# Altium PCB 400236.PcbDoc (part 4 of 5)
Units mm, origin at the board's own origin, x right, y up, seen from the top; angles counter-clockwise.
Board outline 136.53 x 63.5 mm, 4 copper layers (Top Layer, Mid-Layer 1, Mid-Layer 2, Bottom Layer), stack 1.505 mm thick; 340 components, 230 nets, 1369 pads, 1292 vias.
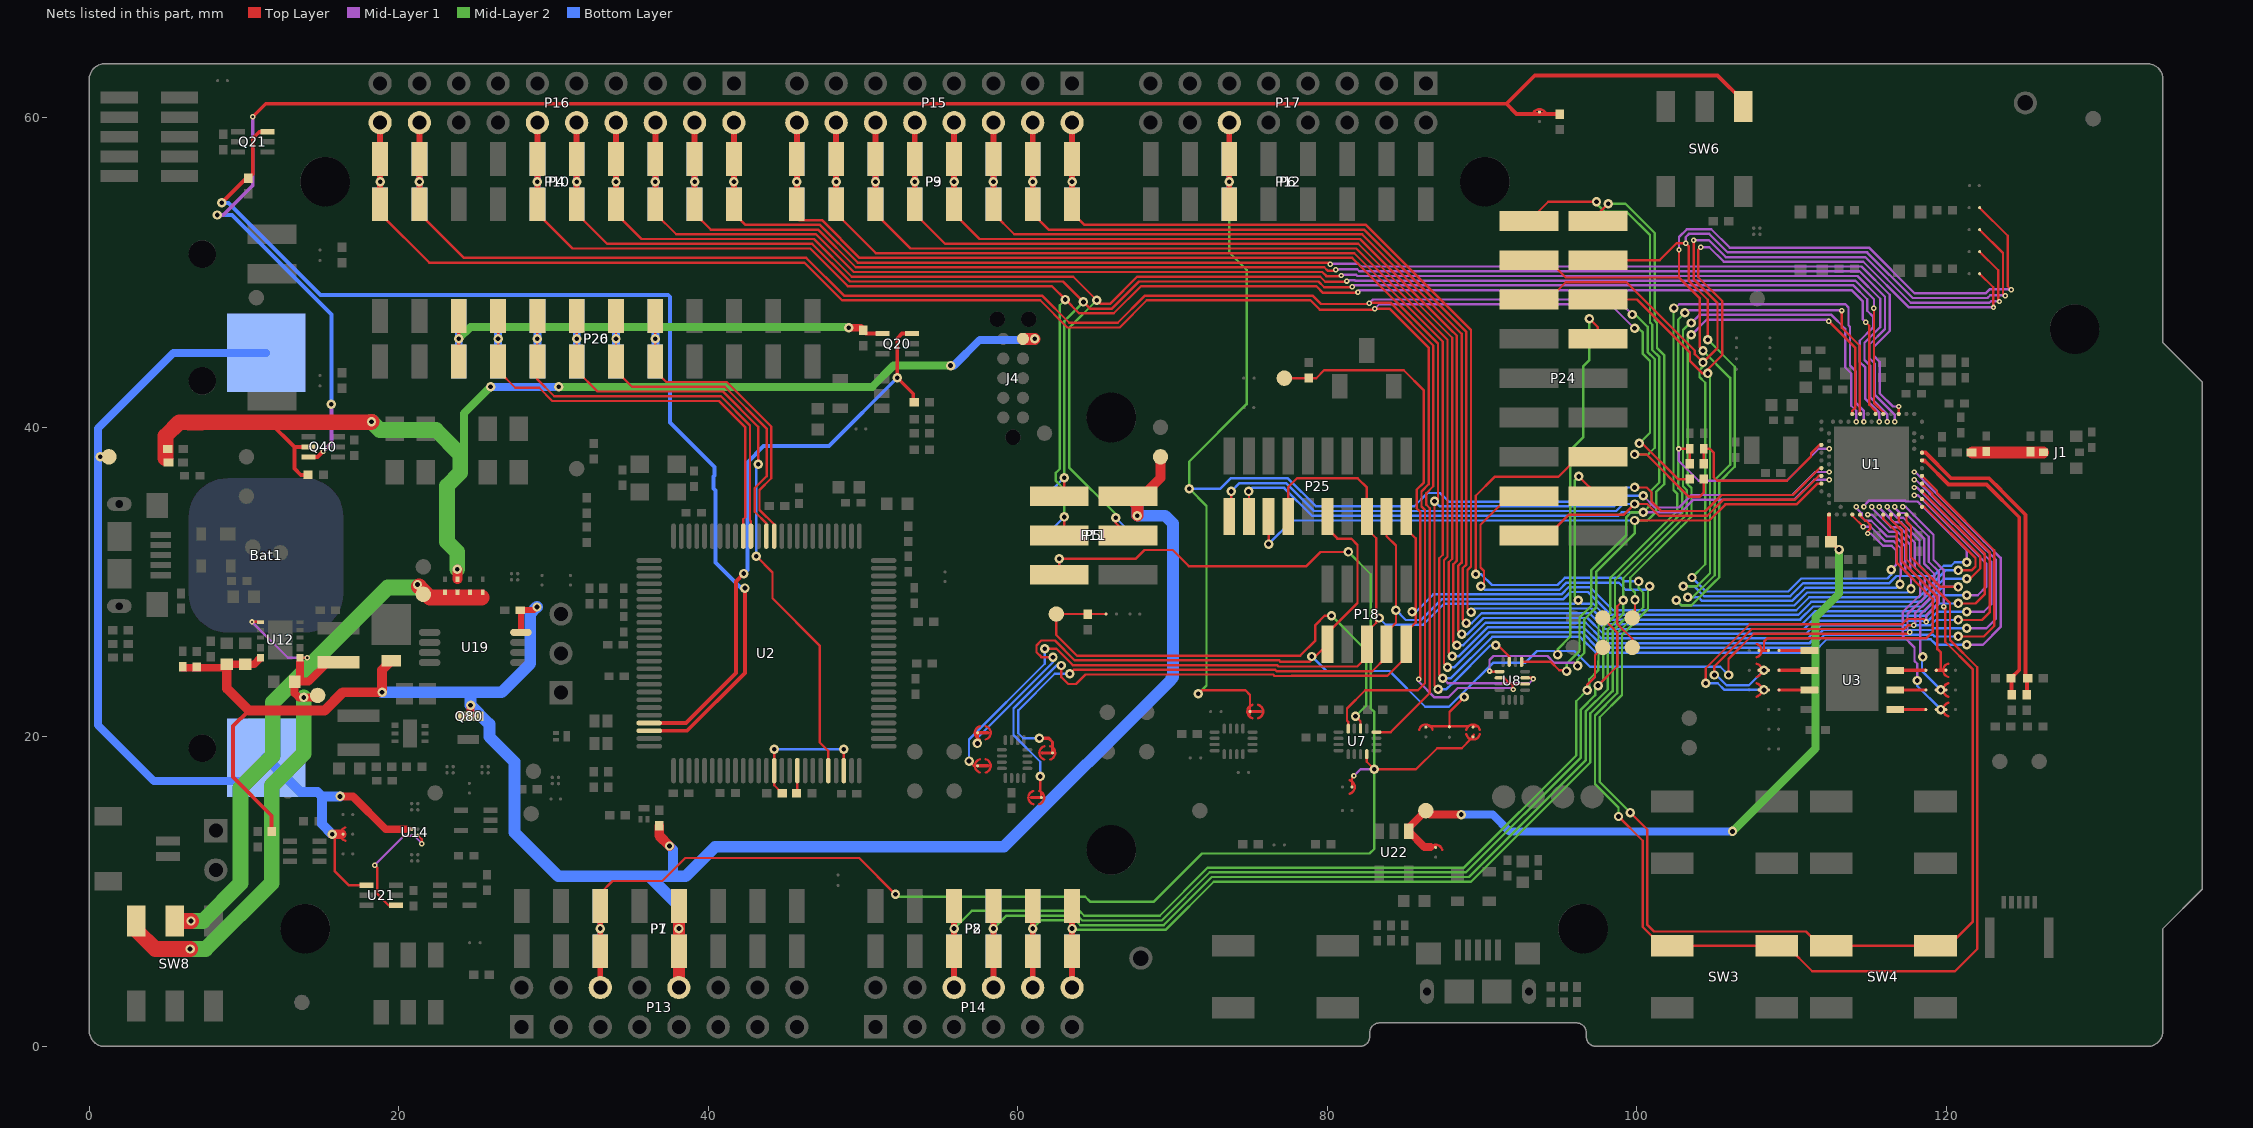
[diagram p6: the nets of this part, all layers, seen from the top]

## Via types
v1: diameter 0.61, hole 0.305, Top Layer to Bottom Layer, tented both sides, 1088 vias
v2: diameter 0.35, hole 0.15, Top Layer to Mid-Layer 1, tented both sides, 180 vias
v3: diameter 0.61, hole 0.305, Top Layer to Bottom Layer, 24 vias

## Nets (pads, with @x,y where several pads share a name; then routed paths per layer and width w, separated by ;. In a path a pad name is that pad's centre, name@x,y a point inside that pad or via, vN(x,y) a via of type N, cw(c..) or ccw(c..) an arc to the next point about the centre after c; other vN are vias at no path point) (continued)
P0.08: P6.6 P12.6 P17.12 SB52.1 U1.N1 | length 93.5
  Top Layer w0.15: 110.082,35.636 111.814,37.367 U1.N1@111.914,37.367
  Top Layer w0.152: v1(71.653,22.784) 71.884,23.014 74.7,23.014 74.999,22.716 74.999,21.463 ; v1(99.847,36.119) 100.627,36.119 100.94,35.806 100.94,35.204 101.548,34.595 104.42,34.595 105.462,35.636 110.082,35.636
  Top Layer w0.381: P6.6@73.66,54.712 v1(73.66,55.88) P6.6@73.66,57.345 P17.12@73.66,59.69
  Mid-Layer 2 w0.152: v1(71.653,22.784) 72.187,23.317 72.187,34.925 v1(71.069,36.043) 71.069,37.794 74.778,41.503 74.778,50.19 73.66,51.308 v1(73.66,55.88)
  Bottom Layer w0.152: v1(71.069,36.043) 73.083,36.043 73.744,36.703 77.452,36.703 79.256,34.9 85.606,34.9 86.469,35.763 87.277,35.763 87.835,35.204 98.405,35.204 99.319,36.119 v1(99.847,36.119)
  Bottom Layer w0.381: P12.6@73.66,54.415 v1(73.66,55.88) P12.6@73.66,57.345
P0.09/NFC1: R43.2 R44.2 U1.L24 | length 19.6
  Top Layer w0.25: U1.L24@118.414,37.867 118.569,37.867 118.569,37.782 118.655,37.782 120.125,36.311 122.585,36.311 124.699,34.197 124.699,24.33 R43.2@124.169,23.8 124.206,23.762 R44.2@124.206,22.725
P0.10/NFC2: R45.2 R46.2 U1.J24 | length 20
  Top Layer w0.25: U1.J24@118.414,38.367 118.638,38.367 120.292,36.714 122.751,36.714 123.484,35.981 123.484,35.971 125.101,34.354 125.101,23.95 R45.2@125.251,23.8 ; R46.2@125.197,22.725 R45.2@125.197,23.745
P0.11: P24.1 P25.18 U1.T2 U8.5 | length 84.7
  Top Layer w0.152: v1(74.905,35.865) 74.93,35.839 P25.18@74.93,34.245 ; U8.5@92.548,24.847 94.437,24.847 94.976,24.308 95.402,24.308 v1(95.453,24.257) ; P24.1@93.027,53.34 94.272,54.585 v1(97.384,54.585)
  Mid-Layer 1 w0.152: v1(100.406,34.519) 102.84,34.519 103.653,35.331 110.179,35.331 111.465,36.617 v2(112.414,36.617)
  Mid-Layer 2 w0.152: v1(95.453,24.257) 95.453,24.714 96.291,25.552 96.291,27.72 97.053,28.482 97.053,30.784 99.314,33.045 99.314,34.206 99.626,34.519 v1(100.406,34.519) 100.937,35.05 100.937,35.945 101.448,36.455 101.448,44.547 100.99,45.004 100.99,46.627 100.838,46.78 100.838,52.426 99.34,53.924 97.925,53.924 97.384,54.465 v1(97.384,54.585)
  Bottom Layer w0.152: v1(74.905,35.865) 75.133,36.093 77.2,36.093 79.003,34.29 98.784,34.29 99.012,34.519 v1(100.406,34.519)
P0.12: P24.2 P25.16 U1.U1 U8.9 | length 82.8
  Top Layer w0.15: 110.16,35.027 110.315,35.027 111.656,36.367 U1.U1@111.914,36.367
  Top Layer w0.152: v1(76.2,32.461) P25.16@76.2,34.245 ; v2(90.475,24.257) 90.51,24.222 U8.9@91.123,24.222 ; P24.2@97.472,53.34 97.472,53.784 v1(98.146,54.458) ; v1(99.847,33.985) 104.673,33.985 105.714,35.027 110.16,35.027
  Mid-Layer 1 w0.152: v2(90.475,24.257) 90.475,24.97 90.73,25.226 94.213,25.226 94.648,24.79 95.961,24.79 v1(96.164,24.587)
  Mid-Layer 2 w0.152: v1@96.139,24.587 96.139,24.969 96.596,25.426 96.596,27.594 97.358,28.356 97.358,30.658 99.847,33.147 v1(99.847,33.985) 100.686,33.985 101.24,34.539 101.24,35.819 101.752,36.332 101.752,44.673 101.295,45.13 101.295,46.754 101.143,46.906 101.143,52.553 99.238,54.458 v1(98.146,54.458)
  Bottom Layer w0.152: v1(76.2,32.461) 77.724,33.985 v1(99.847,33.985)
P0.13: P24.3 SB5.1 U1.AD8 | length 86
  Top Layer w0.152: P24.3@93.497,50.8 94.285,50.8 95.402,49.682 102.718,49.682 ; v2(102.718,51.486) 102.718,49.682 ; v1(104.267,44.958) 104.046,45.179 104.046,48.354 102.718,49.682 ; U1.AD8@113.914,34.367 113.914,34.295 v2(114.63,33.579) ; SB5.1@122.139,54.197 123.952,52.384 123.952,49.124 v2(124.181,48.895)
  Mid-Layer 1 w0.152: v2(102.718,51.486) 102.718,52.299 103.226,52.807 104.8,52.807 105.994,51.613 114.99,51.613 117.944,48.659 122.522,48.659 122.778,48.915 124.16,48.915 v2(124.181,48.895) ; v2(114.63,33.579) 115.102,33.579 116.03,32.651 116.578,32.651 117.041,32.188 117.041,30.427 116.992,30.378 v1(116.992,29.87)
  Mid-Layer 2 w0.152: v1(103.276,29.032) 103.607,29.032 105.022,30.447 105.022,36.597 106.017,37.592 106.017,43.2 104.267,44.95 v1(104.267,44.958)
  Bottom Layer w0.152: v1(103.276,29.032) 103.97,29.032 104.211,28.792 110.022,28.792 110.402,29.171 110.419,29.171 110.882,29.635 116.757,29.635 v1(116.992,29.87)
P0.14: P24.4 SB6.1 U1.AC9 | length 84.1
  Top Layer w0.152: P24.4@97.472,50.8 101.461,50.8 102.553,51.892 v2(103.149,51.892) 103.353,51.689 103.353,49.468 104.572,48.249 v1(104.572,45.669) ; SB6.1@122.139,52.774 123.647,51.266 123.647,48.666 v2(123.8,48.514)
  Mid-Layer 1 w0.152: v2(103.149,51.892) 103.149,52.299 103.352,52.502 104.674,52.502 105.868,51.308 114.867,51.308 117.818,48.357 122.647,48.357 122.825,48.534 123.779,48.534 v2(123.8,48.514) ; v2(114.164,34.867) 114.164,34.8 114.512,34.451 114.512,34.201 114.747,33.966 115.142,33.966 116.155,32.953 116.703,32.953 117.343,32.313 117.343,30.699 117.704,30.338 v1(117.704,29.566)
  Mid-Layer 2 w0.152: v1(102.54,28.829) 102.868,28.501 103.507,28.501 104.978,29.972 104.978,29.976 105.324,30.322 105.324,36.471 106.32,37.467 106.32,43.921 v1(104.572,45.669)
  Bottom Layer w0.152: v1(102.54,28.829) 102.88,28.489 110.164,28.489 111.008,29.333 117.471,29.333 v1(117.704,29.566)
P0.15: P24.5 SB7.1 U1.AD10 | length 81.9
  Top Layer w0.152: P24.5@93.027,48.26 94.285,48.26 95.402,49.378 99.314,49.378 103.734,44.958 103.734,44.737 104.267,44.204 v1(104.267,44.196) 105.207,45.136 105.207,48.034 103.657,49.584 v2(103.657,52.095) ; U1.AD10@114.414,34.367 114.414,34.3 114.747,33.966 114.81,33.966 115.062,33.714 115.062,33.435 114.91,33.282 v2(114.91,33.147) ; SB7.1@122.139,51.352 123.342,50.149 123.342,48.209 v2(123.419,48.133)
  Mid-Layer 1 w0.152: v2(103.657,52.095) 104.649,52.095 105.742,51.003 114.744,51.003 117.693,48.054 122.773,48.054 122.871,48.153 123.398,48.153 v2(123.419,48.133) ; v2(114.91,33.147) 115.106,33.147 115.905,32.348 116.452,32.348 116.738,32.063 116.738,31.115 v1(116.434,30.81)
  Mid-Layer 2 w0.152: v1(103.556,30.302) 104.417,31.163 104.417,42.889 104.041,43.265 104.041,43.705 104.267,43.931 v1(104.267,44.196)
  Bottom Layer w0.152: v1(103.556,30.302) 104.462,29.396 109.772,29.396 110.615,30.24 116.183,30.24 116.434,30.49 v1(116.434,30.81)
P0.16: P24.6 SB8.1 U1.AC11 | length 85.2
  Top Layer w0.152: P24.6@97.472,48.26 100.011,48.26 103.429,44.842 103.429,44.28 104.224,43.485 v1(104.572,43.485) 104.572,43.746 105.504,44.679 105.504,48.158 103.962,49.7 103.962,51.486 v2(104.115,51.638) ; SB8.1@122.139,49.93 123.015,49.054 123.015,47.775 v2(123.038,47.752)
  Mid-Layer 1 w0.152: v2(104.115,51.638) 104.676,51.638 105.615,50.698 114.622,50.698 117.568,47.752 v2(123.038,47.752) ; v2(114.664,34.867) 114.664,34.935 114.997,35.269 117.33,35.269 117.382,35.216 118.128,35.216 118.277,35.067 121.31,32.034 v1(121.31,31.293)
  Mid-Layer 2 w0.152: v1(102.997,29.743) 103.89,29.743 104.719,30.573 104.719,43.337 v1(104.572,43.485)
  Bottom Layer w0.152: v1(102.997,29.743) 103.687,29.743 104.336,29.094 109.897,29.094 110.74,29.937 116.308,29.937 116.772,30.401 119.157,30.401 119.817,31.062 120.3,31.062 120.531,31.293 v1(121.31,31.293)
P0.17: SB13.1 SB23.1 U1.AD12 | length 16.6
  Top Layer w0.203: SB13.1@119.337,21.768 v1(119.634,21.768) SB23.1@119.957,21.768
  Mid-Layer 1 w0.152: v2(114.914,34.367) 115.169,34.367 116.28,33.256 116.828,33.256 117.646,32.438 117.646,30.824 118.3,30.17 118.3,29.189 117.178,28.067 117.178,26.535 117.935,25.779 117.935,24.901 118.11,24.725 v1(118.11,23.647)
  Bottom Layer w0.152: v1(118.11,23.647) 118.11,23.292 v1(119.634,21.768)
P0.18/RESET: P18.10 P24.8 P25.10 SB42.2 SB44.2 SB45.2 SB56.1 U1.AC13 | length 123.7
  Top Layer w0.152: v1(62.272,25.155) 61.517,25.155 61.199,25.473 61.199,25.915 61.512,26.227 62.395,26.227 63.678,24.945 76.877,24.945 76.963,24.858 78.878,24.858 P18.10@80.01,25.99 80.01,26.717 81.94,28.647 81.94,32.41 81.534,32.816 80.645,32.816 80.01,33.452 P25.10@80.01,34.245 ; 86.589,20.683 86.668,20.683 SB42.2@87.884,20.683 ; v1(88.849,22.581) 87.884,21.615 SB42.2@87.884,20.683 ; 89.1,20.683 SB42.2@87.884,20.683 ; SB44.2@89.408,20.683 89.716,20.683 ; v1(96.926,47.015) 97.472,46.469 P24.8@97.472,45.72 ; v1(105.918,24.003) 105.918,25.044 107.544,26.67 117.526,26.67 v2(117.627,26.772)
  Top Layer w0.203: 57.396,19.916 SB56.1@57.396,20.269
  Mid-Layer 1 w0.152: v2(115.164,34.867) 115.164,34.8 116.406,33.558 116.954,33.558 117.948,32.564 117.948,30.949 118.602,30.295 118.602,29.063 117.48,27.941 117.48,26.919 v2(117.627,26.772)
  Mid-Layer 2 w0.152: v1(94.869,25.324) 94.869,25.658 95.682,26.471 95.682,38.516 96.52,39.354 96.52,43.942 96.926,44.348 v1(96.926,47.015)
  Bottom Layer w0.152: v1(57.389,19.583) 57.389,19.949 62.272,24.832 v1(62.272,25.155) ; v1(78.994,25.197) 79.934,24.257 84.01,24.257 86.322,21.946 87.856,21.946 v1@88.67,22.76 ; v1(88.849,22.581) v1@88.67,22.76 ; v1(94.869,25.324) 94.64,25.552 93.539,25.552 92.774,24.787 90.697,24.787 v1@88.67,22.76 ; v1@94.869,25.552 95.95,25.552 96.964,24.539 105.382,24.539 v1(105.918,24.003)
P0.19: SB11.1 SB21.1 U1.AC15 | length 28.7
  Top Layer w0.152: v1(105.004,24.003) 105.004,24.562 107.417,26.975 117.263,26.975 117.504,27.216 v2(117.881,27.216)
  Top Layer w0.203: SB21.1@107.881,24.308 108.056,24.308 v1(108.204,24.308) SB11.1@108.501,24.308
  Mid-Layer 1 w0.152: v2(115.664,34.867) 115.664,34.8 116.603,33.86 117.079,33.86 118.25,32.689 118.25,31.074 118.905,30.42 118.905,28.938 117.991,28.024 117.991,27.325 v2(117.881,27.216)
  Bottom Layer w0.152: v1(105.004,24.003) 105.122,24.003 105.783,23.343 107.239,23.343 v1(108.204,24.308)
P0.20: SB12.1 SB22.1 U1.AD16 | length 21.3
  Top Layer w0.152: SB22.1@107.881,25.578 108.204,25.578 ; SB12.1@108.501,25.578 108.204,25.578 ; U1.AD16@115.914,34.367 115.914,34.099 116.792,33.221 116.792,32.004 116.794,32.002 116.794,31.234 119.108,28.92 119.108,26.805 118.669,26.365 108.41,26.365 108.204,26.16 108.204,25.578
P0.21: SB14.1 SB24.1 U1.AC17 | length 14.9
  Top Layer w0.203: SB14.1@119.337,23.038 v1(119.634,23.038) SB24.1@119.957,23.038
  Mid-Layer 1 w0.152: v2(116.164,34.867) 116.164,34.8 116.801,34.163 117.204,34.163 118.553,32.814 118.553,31.2 119.207,30.545 119.207,28.813 118.293,27.899 118.293,25.293 118.415,25.171 v1@118.44,25.197
  Bottom Layer w0.152: v1@118.415,25.171 118.415,24.257 v1(119.634,23.038)
  other v1: 118.466,25.171
P0.22: SB15.1 SB25.1 U1.AD18 | length 12
  Top Layer w0.152: U1.AD18@116.414,34.367 116.414,34.03 117.096,33.347 117.096,31.359 119.411,29.045 119.411,25.674 119.634,25.451 119.634,24.308
  Top Layer w0.203: SB15.1@119.337,24.308 119.634,24.308 SB25.1@119.957,24.308
P0.23: SB10.1 SB20.1 U1.AC19 | length 30.3
  Top Layer w0.152: v1(104.445,23.47) 104.445,24.434 107.29,27.28 117.14,27.28 117.478,27.617 118.509,27.617 v2(118.694,27.432)
  Top Layer w0.203: SB20.1@107.881,23.038 v1(108.204,23.038) SB10.1@108.501,23.038
  Mid-Layer 1 w0.152: v2(116.664,34.867) 116.664,34.8 116.998,34.465 117.329,34.465 118.855,32.939 118.855,31.325 119.509,30.671 119.509,28.688 118.694,27.872 v2(118.694,27.432)
  Bottom Layer w0.152: v1(104.445,23.47) 105.225,23.47 105.656,23.038 v1(108.204,23.038)
P0.24: P24.14 SW3.2 U1.AD20 | length 103.7
  Top Layer w0.152: v1(89.586,30.505) 89.586,35.585 90.805,36.805 94.92,36.805 96.215,38.1 P24.14@97.472,38.1 ; v1(98.806,14.859) 100.37,13.295 100.37,7.72 101.588,6.502 SW3.2@102.278,6.502 SW3.2@109.028,6.502 109.691,6.502 111.328,4.864 120.548,4.864 121.99,6.305 121.99,24.503 120.221,26.272 120.221,28.663 117.401,31.482 117.401,33.473 116.914,33.961 U1.AD20@116.914,34.367
  Mid-Layer 2 w0.152: v1(98.806,14.859) 98.806,15.447 97.29,16.963 97.29,21.394 98.73,22.834 98.73,26.71 98.977,26.957 98.98,26.957 100.404,28.38 100.404,29.319 100.101,29.621 v1(100.101,30.048)
  Bottom Layer w0.152: v1(89.586,30.505) 89.941,30.505 90.627,29.82 94.871,29.82 95.328,30.277 98.948,30.277 99.177,30.048 v1(100.101,30.048)
P0.25: P24.15 SW4.2 U1.AC21 | length 95
  Top Layer w0.152: v1(89.916,29.743) 90.119,29.947 90.119,30.726 89.891,30.955 89.891,33.706 91.745,35.56 P24.15@93.027,35.56 ; v1(99.568,15.113) 100.675,14.006 100.675,7.846 101.09,7.43 110.921,7.43 111.85,6.502 SW4.2@112.54,6.502 SW4.2@119.29,6.502 120.137,6.502 121.685,8.049 121.685,24.38 119.918,26.147 119.918,28.316 v2(119.812,28.423) ; v2@119.812,28.448 v2@119.825,28.435
  Mid-Layer 1 w0.152: v2(117.164,34.867) 117.355,34.867 119.158,33.065 119.158,31.45 119.812,30.796 v2(119.812,28.423)
  Mid-Layer 2 w0.152: v1(99.568,15.113) 97.595,17.086 97.595,21.268 99.035,22.708 99.035,26.584 100.711,28.26 100.711,29.642 v1(100.813,29.743)
  Bottom Layer w0.152: v1(89.916,29.743) 90.145,29.515 94.997,29.515 95.455,29.972 98.822,29.972 99.279,29.515 100.584,29.515 v1(100.813,29.743)
P0.26: C51.2 R1.2 U1.G1 | length 11.4
  Top Layer w0.15: 109.55,36.551 109.674,36.551 109.675,36.552 111.244,38.12 111.244,38.214
  Top Layer w0.152: R1.2@104.318,37.66 C51.2@104.318,38.616 104.716,38.616 104.953,38.379 104.953,36.779 105.181,36.551 109.55,36.551 ; 111.244,38.214 111.244,38.32 111.791,38.867 U1.G1@111.914,38.867
P0.27: C52.1 R2.2 U1.H2 | length 13.5
  Top Layer w0.152: v2(102.692,38.608) 102.7,38.616 C52.1@103.403,38.616 R2.2@103.403,37.66
  Mid-Layer 1 w0.152: v2(102.692,38.608) 102.692,37.846 103.988,36.551 109.674,36.551 111.741,38.617 v2@112.378,38.617
  other v2: 112.414,38.617
P0.28/AIN4: P2.3 P8.3 P14.6 TP44.1 U1.B11 | length 107.4
  Top Layer w0.152: v1(96.774,23.012) 96.774,23.354 97.285,23.865 97.285,25.276 TP44.1@97.79,25.781
  Top Layer w0.381: P14.6@55.88,3.81 P2.3@55.88,6.155 v1(55.88,7.62) P2.3@55.88,9.085
  Mid-Layer 1 w0.152: v1@102.438,47.658 102.733,47.953 113.466,47.953 113.665,47.754 113.665,46.598 113.767,46.496 113.767,43.993 114.151,43.608 114.151,41.579 114.664,41.067 v2(114.664,40.367)
  Mid-Layer 2 w0.152: v1(55.88,7.62) 57.023,8.763 63.973,8.763 64.289,8.448 69.164,8.448 72.273,11.557 88.824,11.557 96.071,18.804 96.071,22.31 v1(96.774,23.012) 96.915,23.153 96.915,23.728 97.506,24.319 97.506,24.887 97.511,24.892 97.511,27.215 98.273,27.977 98.273,30.279 102.614,34.62 102.614,35.704 102.36,35.958 102.36,42.339 102.362,42.342 102.362,47.683 v1(102.387,47.709)
  Bottom Layer w0.381: P8.3@55.88,6.155 v1(55.88,7.62) P8.3@55.88,9.085
P0.29/AIN5: P2.4 P8.4 P14.8 TP45.1 U1.A10 | length 106
  Top Layer w0.152: v1(97.485,23.317) 98.73,24.562 98.73,26.746 TP45.1@97.79,27.686 ; v2(113.233,47.549) 113.233,46.445 114.397,45.281 114.397,40.884 U1.A10@114.414,40.867 ; v2@113.309,47.549 v2@113.309,47.574
  Top Layer w0.381: P14.8@58.42,3.81 P2.4@58.42,6.155 v1(58.42,7.62) P2.4@58.42,9.085
  Mid-Layer 1 w0.152: v1(103.099,47.404) 103.269,47.574 v2@113.233,47.574
  Mid-Layer 2 w0.152: v1(58.42,7.62) 59.258,8.458 63.847,8.458 64.162,8.143 69.29,8.143 72.399,11.252 88.95,11.252 96.376,18.678 96.376,21.773 97.305,22.702 97.305,23.137 v1(97.485,23.317) 97.815,23.647 97.815,27.089 98.577,27.851 98.577,30.153 102.54,34.115 102.54,34.119 102.916,34.495 102.916,35.829 102.667,36.078 102.667,46.972 v1(103.099,47.404)
  Bottom Layer w0.381: P8.4@58.42,6.155 v1(58.42,7.62) P8.4@58.42,9.652
P0.30/AIN6: P2.5 P8.5 P14.10 TP46.1 U1.B9 | length 101.3
  Top Layer w0.152: v1(99.111,28.829) 98.73,28.448 98.73,27.305 99.695,26.34 TP46.1@99.695,25.781
  Top Layer w0.381: P14.10@60.96,3.81 P2.5@60.96,6.155 v1(60.96,7.62) P2.5@60.96,9.085
  Mid-Layer 1 w0.152: v1(103.505,46.744) 104.033,47.272 112.56,47.272 113.462,46.37 113.462,43.867 113.846,43.482 113.846,41.399 114.164,41.081 v2(114.164,40.367)
  Mid-Layer 2 w0.152: v1(60.96,7.62) 61.493,8.153 63.721,8.153 64.036,7.838 69.417,7.838 72.526,10.947 89.154,10.947 96.681,18.474 96.681,21.647 98.12,23.086 98.12,26.962 99.111,27.953 v1(99.111,28.829) 99.111,30.255 103.218,34.363 103.218,35.954 102.972,36.201 102.972,46.301 103.541,46.871 v1@103.657,46.871
  Bottom Layer w0.381: P8.5@60.96,6.155 v1(60.96,7.62) P8.5@60.96,9.652
P0.31/AIN7: P2.6 P8.6 P14.12 TP47.1 U1.A8 | length 94.5
  Top Layer w0.152: TP47.1@99.695,27.686 99.873,27.864 v1(99.873,28.854) ; v2@112.446,46.863 112.446,46.801 114.092,45.155 114.092,41.256 113.914,41.077 U1.A8@113.914,40.867
  Top Layer w0.381: P14.12@63.5,3.81 P2.6@63.5,6.155 v1(63.5,7.62) P2.6@63.5,9.085
  Mid-Layer 1 w0.152: v1@103.53,46.109 103.657,46.109 104.513,46.965 112.344,46.965 v2@112.446,46.863
  Mid-Layer 2 w0.152: v1(63.5,7.62) 63.587,7.533 69.543,7.533 72.652,10.643 89.28,10.643 96.986,18.348 96.986,21.521 98.425,22.96 98.425,26.836 99.873,28.284 v1(99.873,28.854) 99.873,29.335 99.57,29.637 99.57,30.284 102.868,33.581 102.868,33.584 103.521,34.237 103.521,36.08 103.274,36.326 103.274,40.968 103.276,40.97 103.276,45.855 v1@103.53,46.109 ; v1@103.594,46.045 v1@103.657,46.109
  Bottom Layer w0.381: P8.6@63.5,6.155 v1(63.5,7.62) P8.6@63.5,9.085
  other v1: 103.505,45.982
  other v2: 112.395,46.863
P1.00: P18.6 P24.16 P25.6 P25.14 SB57.1 U1.AD22 | length 106.4
  Top Layer w0.152: v1(56.845,18.44) 57.15,18.136 57.222,18.136 SB57.1@57.396,18.136 ; v1(61.733,25.694) 62.498,25.694 63.552,24.64 76.75,24.64 76.837,24.554 81.932,24.554 82.55,25.171 P18.6@82.55,25.99 82.55,26.773 83.159,27.381 83.159,32.843 82.55,33.452 P25.6@82.55,34.245 82.55,36.119 81.952,36.716 78.042,36.716 77.47,36.144 P25.14@77.47,34.245 ; v1(96.241,36.83) P24.16@97.472,35.598 ; U1.AD22@117.414,34.367 117.414,33.892 117.704,33.602 117.704,31.607 119.618,29.693 v1(120.752,29.693)
  Mid-Layer 2 w0.152: v1(96.215,28.829) 95.987,29.058 95.987,36.576 v1(96.241,36.83)
  Bottom Layer w0.152: v1(56.845,18.44) 56.845,19.837 61.738,24.73 61.738,25.689 v1(61.733,25.694) ; v1(83.337,27.686) 83.768,27.254 86.182,27.254 87.528,28.6 95.961,28.6 ; v1(96.215,28.829) 96.444,28.6 97.179,28.6 98.2,27.58 106.02,27.58 106.022,27.582 110.54,27.582 111.383,28.425 118.464,28.425 119.731,29.693 v1(120.752,29.693)
P1.01: P3.1 P9.1 P15.2 U1.Y23 | length 99.5
  Top Layer w0.152: P3.1@63.5,54.415 63.5,53.899 64.313,53.086 82.493,53.086 89.281,46.298 89.281,31.013 89.052,30.785 89.052,28.296 v1(89.281,28.067)
  Top Layer w0.381: P3.1@63.5,54.415 v1(63.5,55.88) P3.1@63.5,57.345 P15.2@63.5,59.69
  Mid-Layer 1 w0.152: v2(117.914,35.617) 118.154,35.617 122.58,31.191 122.58,29.718 122.022,29.159 v1(121.31,29.159)
  Bottom Layer w0.152: v1(89.281,28.067) 89.51,28.296 97.056,28.296 98.074,27.277 107.694,27.277 107.696,27.28 110.665,27.28 111.509,28.123 118.589,28.123 119.625,29.159 v1(121.31,29.159)
  Bottom Layer w0.381: P9.1@63.5,53.807 v1(63.5,55.88) P9.1@63.5,57.345
P1.02: P3.2 P9.2 P15.4 U1.W24 | length 102.5
  Top Layer w0.152: P3.2@60.96,54.415 60.96,53.797 61.976,52.781 82.367,52.781 88.976,46.172 88.976,31.14 88.748,30.911 88.748,27.584 v1(88.976,27.356) ; U1.W24@118.414,35.867 118.431,35.867 118.78,35.519 118.78,35.515 122.479,31.816 122.479,29.235 121.869,28.626 v1(120.752,28.626)
  Top Layer w0.381: P3.2@60.96,54.415 v1(60.96,55.88) P3.2@60.96,57.345 P15.4@60.96,59.69
  Bottom Layer w0.152: v1(88.976,27.356) 89.324,27.356 89.959,27.991 96.933,27.991 97.949,26.975 110.788,26.975 111.634,27.821 118.714,27.821 119.519,28.626 v1(120.752,28.626)
  Bottom Layer w0.381: P9.2@60.96,54.415 v1(60.96,55.88) P9.2@60.96,57.345
P1.03: P3.3 P9.3 P15.6 U1.V23 | length 107.4
  Top Layer w0.152: P3.3@58.42,54.415 58.42,53.823 59.766,52.476 82.241,52.476 88.671,46.046 88.671,31.266 88.443,31.037 88.443,26.873 v1(88.671,26.645)
  Top Layer w0.381: P3.3@58.42,54.415 v1(58.42,55.88) P3.3@58.42,57.345 P15.6@58.42,59.69
  Mid-Layer 1 w0.152: v2(117.914,36.117) 118.085,36.117 122.885,31.317 122.885,28.575 122.403,28.092 v1(121.31,28.092)
  Bottom Layer w0.152: v1(88.671,26.645) 89.052,26.645 90.094,27.686 96.81,27.686 97.826,26.67 110.911,26.67 111.759,27.518 118.839,27.518 119.414,28.092 v1(121.31,28.092)
  Bottom Layer w0.381: P9.3@58.42,54.415 v1(58.42,55.88) P9.3@58.42,57.345
P1.04: P3.4 P9.4 P15.8 U1.U24 | length 111
  Top Layer w0.152: P3.4@55.88,54.415 55.88,53.823 57.531,52.172 82.114,52.172 87.956,46.33 88.367,45.919 88.367,31.392 88.138,31.164 88.138,26.162 v1(88.367,25.933) ; U1.U24@118.414,36.367 118.414,36.307 118.487,36.233 118.565,36.233 119.084,35.714 119.084,35.641 122.783,31.942 122.783,28.041 122.301,27.559 v1(120.752,27.559)
  Top Layer w0.381: P3.4@55.88,54.415 v1(55.88,55.88) P3.4@55.88,57.345 P15.8@55.88,59.69
  Bottom Layer w0.152: v1(88.367,25.933) 88.773,25.933 90.221,27.381 96.687,27.381 97.703,26.365 111.034,26.365 111.885,27.216 118.965,27.216 119.308,27.559 v1(120.752,27.559)
  Bottom Layer w0.381: P9.4@55.88,54.415 v1(55.88,55.88) P9.4@55.88,57.345
P1.05: P3.5 P9.5 P15.10 U1.T23 | length 115.8
  Top Layer w0.152: P3.5@53.34,54.415 53.34,53.823 55.296,51.867 81.988,51.867 88.062,45.793 88.062,31.518 87.833,31.29 87.833,31.013 87.833,26.848 87.833,25.451 v1(88.062,25.222)
  Top Layer w0.381: P3.5@53.34,54.415 v1(53.34,55.88) P3.5@53.34,57.345 P15.10@53.34,59.69
  Mid-Layer 1 w0.152: v2(117.914,36.617) 118.016,36.617 119.684,34.95 119.686,34.95 122.072,32.564 122.072,32.561 123.19,31.444 123.19,27.635 122.58,27.026 v1(121.31,27.026)
  Bottom Layer w0.152: v1(88.062,25.222) 88.493,25.222 90.347,27.076 96.564,27.076 97.58,26.06 111.157,26.06 112.01,26.913 119.09,26.913 119.202,27.026 v1(121.31,27.026)
  Bottom Layer w0.381: P9.5@53.34,54.415 v1(53.34,55.88) P9.5@53.34,57.345
P1.06: P3.6 P9.6 P15.12 U1.R24 | length 119.5
  Top Layer w0.152: P3.6@50.8,54.415 50.8,53.823 53.061,51.562 81.862,51.562 87.757,45.667 87.757,31.645 87.528,31.416 87.528,31.14 87.528,31.115 87.528,26.822 87.528,24.74 v1(87.757,24.511) ; U1.R24@118.414,36.867 118.431,36.867 119.389,35.909 119.389,35.767 123.088,32.068 123.088,27.178 122.403,26.492 v1(120.752,26.492)
  Top Layer w0.381: P3.6@50.8,54.415 v1(50.8,55.88) P3.6@50.8,57.345 P15.12@50.8,59.69
  Bottom Layer w0.152: v1(87.757,24.511) 88.213,24.511 90.473,26.772 96.442,26.772 97.458,25.756 111.28,25.756 112.135,26.611 119.107,26.611 119.225,26.492 v1(120.752,26.492)
  Bottom Layer w0.381: P9.6@50.8,54.415 v1(50.8,55.88) P9.6@50.8,57.345
P1.07: P3.7 P9.7 P15.14 U1.P23 U8.3 | length 130.9
  Top Layer w0.152: P3.7@48.26,54.415 48.26,53.823 50.825,51.257 81.736,51.257 87.452,45.541 87.452,31.771 87.224,31.542 87.224,31.266 87.224,30.989 87.224,24.028 v1(87.452,23.8) ; U8.3@92.773,23.822 93.196,23.822 v2@93.294,23.724
  Top Layer w0.381: P3.7@48.26,54.415 v1(48.26,55.88) P3.7@48.26,57.345 P15.14@48.26,59.69
  Mid-Layer 1 w0.152: v1(87.452,23.8) 87.782,23.47 93.04,23.47 v2@93.294,23.724 ; v2(117.914,37.117) 117.984,37.117 118.515,36.587 118.515,36.552 122.415,32.652 ; v1(121.31,25.959) 122.352,25.959 123.495,27.102 123.495,31.57 122.415,32.649
  Bottom Layer w0.152: v1(87.452,23.8) 87.986,23.8 90.653,26.467 96.319,26.467 97.337,25.448 106.398,25.448 106.401,25.451 111.406,25.451 112.264,26.309 118.975,26.309 119.223,26.06 119.227,26.06 119.328,25.959 v1(121.31,25.959)
  Bottom Layer w0.381: P9.7@48.26,54.415 v1(48.26,55.88) P9.7@48.26,57.345
  other v2: 93.294,23.749
P1.08: P3.8 P9.8 P15.16 U1.P2 U8.7 | length 109.9
  Top Layer w0.152: P3.8@45.72,54.415 45.72,53.543 45.872,53.391 47.339,53.391 49.777,50.952 81.609,50.952 87.147,45.414 v1@87.147,35.23 ; v1(86.919,35.23) 86.919,31.392 86.919,30.863 86.919,23.317 v1(87.147,23.089) ; v1(90.884,25.93) 91.013,25.93 91.748,25.196 U8.7@91.748,24.847
  Top Layer w0.381: P3.8@45.72,54.415 v1(45.72,55.88) P3.8@45.72,57.345 P15.16@45.72,59.69
  Mid-Layer 1 w0.152: v1(100.406,35.585) 101.171,34.821 102.715,34.821 103.53,35.636 110.053,35.636 111.534,37.117 v2(112.414,37.117)
  Bottom Layer w0.152: v1(86.919,35.23) 87.249,34.9 98.531,34.9 99.217,35.585 v1(100.406,35.585) ; v1(87.147,23.089) 87.69,23.089 87.995,23.393 88.01,23.393 90.522,25.905 v1@90.884,25.905
  Bottom Layer w0.381: P9.8@45.72,54.415 v1(45.72,55.88) P9.8@45.72,57.345
P1.09: P24.17 P25.20 U1.R1 | length 51
  Top Layer w0.15: 110.058,35.331 110.203,35.331 111.739,36.867 U1.R1@111.914,36.867
  Top Layer w0.152: P25.20@73.66,33.401 P25.20@73.66,34.245 73.787,34.372 v1(73.787,35.865) ; P24.17@93.027,33.02 94.259,33.02 95.606,34.366 99.162,34.366 v1(99.847,35.052) 100.66,35.052 101.422,34.29 104.546,34.29 105.588,35.331 110.058,35.331
  Bottom Layer w0.152: v1@73.66,35.738 v1(73.787,35.865) 74.32,36.398 77.326,36.398 79.129,34.595 98.658,34.595 99.115,35.052 v1(99.847,35.052)
P1.10: P4.1 P10.1 P16.2 U1.A20 | length 94.7
  Top Layer w0.152: P4.1@41.656,54.415 41.656,53.823 42.393,53.086 47.213,53.086 49.651,50.648 80.061,50.648 v2(80.173,50.535) ; U1.A20@116.914,40.867 v2(116.914,41.351)
  Top Layer w0.381: P4.1@41.656,54.415 v1(41.656,55.88) P4.1@41.656,57.345 P16.2@41.656,59.69
  Mid-Layer 1 w0.152: v2(80.173,50.535) 80.217,50.579 81.994,50.579 82.179,50.394 114.499,50.394 116.327,48.565 116.327,46.229 115.311,45.213 115.311,44.603 115.675,44.24 115.675,42.211 116.534,41.351 v2(116.914,41.351)
  Bottom Layer w0.381: P10.1@41.656,54.415 v1(41.656,55.88) P10.1@41.656,57.345
P1.11: P4.2 P10.2 P16.4 U1.B19 | length 97.2
  Top Layer w0.152: P4.2@39.116,54.415 39.116,53.823 40.157,52.781 47.086,52.781 49.525,50.343 79.795,50.343 80.006,50.131 80.49,50.131 v2(80.533,50.175)
  Top Layer w0.381: P4.2@39.116,54.415 v1(39.116,55.88) P4.2@39.116,57.345 P16.4@39.116,59.69
  Mid-Layer 1 w0.152: v2(80.533,50.175) 80.577,50.219 81.922,50.219 82.052,50.089 114.372,50.089 116.023,48.439 116.023,46.356 115.007,45.34 115.007,44.477 115.37,44.113 115.37,42.084 116.664,40.791 v2(116.664,40.367)
  Bottom Layer w0.381: P10.2@39.116,54.415 v1(39.116,55.88) P10.2@39.116,57.345
P1.12: P4.3 P10.3 P16.6 U1.B17 | length 99.3
  Top Layer w0.152: P4.3@36.576,54.415 36.576,53.823 37.922,52.476 46.96,52.476 49.399,50.038 79.669,50.038 79.935,49.771 80.85,49.771 v2(80.893,49.815)
  Top Layer w0.381: P4.3@36.576,54.415 v1(36.576,55.88) P4.3@36.576,57.345 P16.6@36.576,59.69
  Mid-Layer 1 w0.152: v2(80.893,49.815) 80.937,49.859 81.851,49.859 81.926,49.784 114.246,49.784 115.718,48.312 115.718,46.482 114.702,45.466 114.702,44.351 115.065,43.987 115.065,41.958 116.164,40.86 v2(116.164,40.367)
  Bottom Layer w0.381: P10.3@36.576,54.415 v1(36.576,55.88) P10.3@36.576,57.345
P1.13: P4.4 P5.4 P10.4 P11.4 P16.8 U1.A16 | length 121
  Top Layer w0.152: P4.4@34.036,54.415 34.036,53.823 35.687,52.172 46.834,52.172 49.272,49.733 63.576,49.733 v1(65.1,48.209) 65.329,47.981 65.947,47.981 67.7,49.733 79.542,49.733 79.864,49.412 81.209,49.412 v2(81.253,49.455) ; v1(66.319,34.163) 66.319,33.82 P5.4@67.119,33.02 ; v2(115.291,47.701) 115.311,47.68 115.311,41.584 115.914,40.982 U1.A16@115.914,40.867
  Top Layer w0.381: P4.4@34.036,54.415 v1(34.036,55.88) P4.4@34.036,57.345 P16.8@34.036,59.69
  Mid-Layer 1 w0.152: v2(81.253,49.455) 81.297,49.499 81.78,49.499 81.8,49.479 114.12,49.479 115.316,48.283 115.316,47.727 v2(115.291,47.701)
  Mid-Layer 2 w0.152: v1(65.1,48.209) 65.093,48.209 63.312,46.429 63.312,37.402 66.319,34.394 v1(66.319,34.163)
  Bottom Layer w0.152: v1(66.319,34.163) 67.462,33.02 P11.4@67.722,33.02
  Bottom Layer w0.381: P10.4@34.036,54.415 v1(34.036,55.88) P10.4@34.036,57.345
P1.14: P4.5 P5.1 P10.5 P11.1 P16.10 U1.B15 | length 120.3
  Top Layer w0.152: P4.5@31.496,54.415 31.496,53.823 33.452,51.867 46.708,51.867 49.146,49.428 62.916,49.428 v1(64.237,48.108) 64.668,47.676 66.074,47.676 67.826,49.428 79.416,49.428 79.793,49.052 81.569,49.052 v2(81.613,49.095) ; P5.1@62.674,35.56 62.992,35.878 v1(62.992,36.754)
  Top Layer w0.381: P4.5@31.496,54.415 v1(31.496,55.88) P4.5@31.496,57.345 P16.10@31.496,59.69
  Mid-Layer 1 w0.152: v2(81.613,49.095) 81.692,49.174 113.994,49.174 114.884,48.284 114.884,47.537 115.252,47.169 115.252,46.447 114.397,45.592 114.397,44.225 114.761,43.861 114.761,41.832 115.664,40.929 v2(115.664,40.367)
  Mid-Layer 2 w0.152: v1(62.992,36.754) 63.007,36.769 63.007,46.878 v1(64.237,48.108)
  Bottom Layer w0.152: P11.1@61.473,35.56 P11.1@62.072,35.56 62.072,35.834 v1(62.992,36.754)
  Bottom Layer w0.381: P10.5@31.496,54.415 v1(31.496,55.88) P10.5@31.496,57.345
P1.15: P4.6 P5.3 P10.6 P11.3 P16.12 U1.A14 | length 123.4
  Top Layer w0.152: P4.6@28.956,54.415 28.956,53.823 31.217,51.562 46.581,51.562 49.02,49.124 62.205,49.124 v1(63.068,48.26) 63.957,47.371 66.2,47.371 67.952,49.124 79.29,49.124 79.722,48.692 81.929,48.692 v2(81.973,48.735) ; P5.3@62.674,33.02 62.992,33.338 v1(62.992,34.214) ; v2(114.783,46.787) 115.007,46.563 115.007,41.457 115.414,41.05 U1.A14@115.414,40.867
  Top Layer w0.381: P4.6@28.956,54.415 v1(28.956,55.88) P4.6@28.956,57.345 P16.12@28.956,59.69
  Mid-Layer 1 w0.152: v2(81.973,48.735) 82.107,48.87 113.867,48.87 114.579,48.158 114.579,47.012 v2@114.783,46.809
  Mid-Layer 2 w0.152: v1(62.992,34.214) 62.992,35.999 62.459,36.533 62.459,37.069 62.702,37.313 62.702,47.894 v1(63.068,48.26)
  Bottom Layer w0.152: P11.3@62.072,33.02 62.072,33.294 v1(62.992,34.214)
  Bottom Layer w0.381: P10.6@28.956,54.415 v1(28.956,55.88) P10.6@28.956,57.345
PB5: Q20.3 R23.2 U2.97 | length 38.5
  Top Layer w0.254: U2.97@36.179,20.9 38.553,20.9 41.783,24.13 41.783,30.048 v1(42.291,30.556) ; Q20.3@53.155,46.065 52.525,46.065 52.205,45.745 v1(52.205,43.205) 53.238,42.172 53.238,41.631 R23.2@53.297,41.631
  Bottom Layer w0.254: v1(42.291,30.556) 42.52,30.785 42.52,37.744 43.561,38.786 47.786,38.786 v1(52.205,43.205)
PB6: Q21.3 R27.2 U2.98 | length 71.9
  Top Layer w0.254: v1(8.56,54.508) 10.152,56.101 R27.2@10.287,56.101 10.566,56.38 10.566,58.674 10.988,59.095 Q21.3@11.516,59.095 ; U2.98@36.179,20.4 38.628,20.4 42.367,24.139 v1(42.367,29.616)
  Bottom Layer w0.254: v1(8.56,54.508) 9.007,54.508 14.951,48.565 37.394,48.565 37.516,48.443 37.516,40.31 40.386,37.44 40.386,36.893 40.335,36.842 40.335,36.043 40.462,35.916 40.462,31.267 42.113,29.616 v1(42.367,29.616)
QSPI_C\S\: SB13.2 U3.1 | length 2
  Top Layer w0.203: U3.1@116.689,21.768 SB13.2@118.661,21.768
QSPI_CLK: SB11.2 U3.6 | length 2
  Top Layer w0.203: SB11.2@109.177,24.308 U3.6@111.149,24.308
QSPI_DIO0: SB12.2 U3.5 | length 2
  Top Layer w0.203: SB12.2@109.177,25.578 U3.5@111.149,25.578
QSPI_DIO1: SB14.2 U3.2 | length 2
  Top Layer w0.203: U3.2@116.689,23.038 SB14.2@118.661,23.038
QSPI_DIO2: SB15.2 U3.3 | length 2
  Top Layer w0.203: U3.3@116.689,24.308 SB15.2@118.661,24.308
QSPI_DIO3: SB10.2 U3.7 | length 2
  Top Layer w0.203: SB10.2@109.177,23.038 U3.7@111.149,23.038
RESET_PIN: P1.3 P5.5 P7.3 P11.5 P13.6 SB43.2 SB44.1 U7.4 | length 115
  Top Layer w0.152: P1.3@33.02,9.085 33.02,9.906 33.807,10.693 37.023,10.693 38.506,12.177 49.748,12.177 v1(52.095,9.83) ; P5.5@62.679,30.485 v1(62.679,31.506) 67.6,31.506 68.174,32.08 70.002,32.08 71.044,31.039 78.638,31.039 79.553,31.953 v1(81.356,31.953) ; SB43.2@81.592,16.764 81.592,17.117 81.592,17.356 v2@81.737,17.501 ; U7.4@82.54,18.885 82.54,18.399 v1(83.033,17.907) 85.724,17.907 87.091,19.275 88.675,19.275 89.259,19.859 SB44.1@89.408,20.008 ; SB44.1@89.366,20.049 89.459,20.142
  Top Layer w0.381: P13.6@33.02,3.81 P1.3@33.02,6.155 v1(33.02,7.62) P1.3@33.02,9.085
  Mid-Layer 1 w0.152: v2@81.737,17.501 82.144,17.907 v1(83.033,17.907)
  Mid-Layer 2 w0.152: v1(52.095,9.83) 52.248,9.677 64.352,9.677 64.667,9.362 68.785,9.362 71.894,12.471 82.728,12.471 83.033,12.776 v1(83.033,17.907) 83.033,21.608 82.803,21.837 82.803,30.506 v1(81.356,31.953)
  Bottom Layer w0.152: P11.5@62.679,30.48 v1(62.679,31.506)
  Bottom Layer w0.381: P7.3@33.02,6.155 v1(33.02,7.62) P7.3@33.02,9.085
  other v2: 81.712,17.501
RF: C4.2 C22.1 J1.1 L1.2 | length 4.6
  Top Layer w0.762: L1.2@121.681,38.379 J1.1@126.25,38.379
SCL: P4.10 P10.10 P16.20 R2.1 U7.12 | length 140.7
  Top Layer w0.152: P4.10@18.796,54.415 18.796,53.823 21.971,50.648 46.203,50.648 48.641,48.209 61.442,48.209 63.194,46.457 66.579,46.457 68.331,48.209 78.911,48.209 79.508,47.612 83.009,47.612 v2(83.053,47.656) 84.044,47.656 86.538,45.162 86.538,36.321 86.081,35.864 86.081,34.883 86.309,34.654 86.309,23.47 85.852,23.012 82.448,23.012 81.267,21.831 81.267,21.044 81.34,20.971 U7.12@81.34,20.535 ; v1(100.152,38.964) 100.347,38.964 102.65,36.66 R2.1@103.403,36.66
  Top Layer w0.381: P4.10@18.796,54.415 v1(18.796,55.88) P4.10@18.796,57.345 P16.20@18.796,59.69
  Mid-Layer 1 w0.152: v2(83.053,47.656) 83.352,47.955 98.273,47.955 99.822,46.406 v1(99.847,46.406)
  Mid-Layer 2 w0.152: v1(99.847,46.406) 100.101,46.406 100.381,46.126 100.381,44.751 100.838,44.294 100.838,39.649 v1(100.152,38.964)
  Bottom Layer w0.381: P10.10@18.796,54.415 v1(18.796,55.88) P10.10@18.796,57.345
SDA: P4.9 P10.9 P16.18 R1.1 U7.8 | length 141.5
  Top Layer w0.152: P4.9@21.336,54.415 21.336,53.823 24.206,50.952 46.329,50.952 48.767,48.514 61.568,48.514 63.321,46.761 66.452,46.761 68.205,48.514 79.037,48.514 79.579,47.972 82.649,47.972 v2(82.693,48.016) 82.736,48.059 84.071,48.059 86.843,45.288 86.843,36.195 86.385,35.738 86.385,35.009 86.614,34.78 86.614,22.835 84.089,20.31 U7.8@83.165,20.31 ; v1(99.847,38.252) 100.627,38.252 103.37,35.509 104.041,35.509 104.318,35.786 R1.1@104.318,36.66
  Top Layer w0.381: P4.9@21.336,54.415 v1(21.336,55.88) P4.9@21.336,57.345 P16.18@21.336,59.69
  Mid-Layer 1 w0.152: v2(82.693,48.016) 82.937,48.26 98.73,48.26 v1(99.695,47.295)
  Mid-Layer 2 w0.152: v1(99.695,47.295) 99.892,47.295 100.686,46.501 100.686,44.878 101.143,44.42 101.143,38.684 100.711,38.252 v1(99.847,38.252)
  Bottom Layer w0.381: P10.9@21.336,54.415 v1(21.336,55.88) P10.9@21.336,57.345
SH_GND_DETECT: P20.8 P26.8 U2.62 | length 23.2
  Top Layer w0.152: P20.8@36.576,47.185 P20.8@36.576,44.255 36.576,43.637 37.282,42.931 41.193,42.931 44.069,40.056 44.069,36.711 43.307,35.949 43.307,34.671 44.254,33.724 U2.62@44.254,32.975
  Bottom Layer w0.508: P26.8@36.576,44.255 v1(36.576,45.72) P26.8@36.576,47.185
SH_RESET: P20.7 P26.7 U2.63 | length 25.3
  Top Layer w0.152: P20.7@34.036,47.185 P20.7@34.036,44.255 34.036,43.663 35.072,42.627 41.067,42.627 43.764,39.93 43.764,36.837 43.002,36.075 43.002,34.545 43.754,33.793 U2.63@43.754,32.975
  Bottom Layer w0.508: P26.7@34.036,44.255 v1(34.036,45.72) P26.7@34.036,47.185
SH_SWDCLK: P20.5 P26.5 U2.65 | length 29.2
  Top Layer w0.152: P20.5@28.956,47.185 28.956,43.104 30.048,42.012 40.814,42.012 42.697,40.128 42.697,33.987 42.754,33.931 U2.65@42.754,32.975
  Bottom Layer w0.508: P26.5@28.956,44.255 v1(28.956,45.72) P26.5@28.956,47.185
SH_SWDIO: P20.4 P26.4 U2.66 | length 30.9
  Top Layer w0.152: P20.4@26.416,44.255 26.416,43.67 27.53,42.556 29.072,42.556 29.921,41.707 40.688,41.707 42.393,40.002 42.393,34.2 42.254,34.061 U2.66@42.254,32.975 ; P20.4@26.416,44.348 P20.4@26.416,47.185
  Bottom Layer w0.508: P26.4@26.416,44.255 v1(26.416,45.72) P26.4@26.416,47.185
SH_SWO: P20.6 P26.6 U2.21 | length 43.9
  Top Layer w0.152: P20.6@31.496,47.185 v1(31.496,45.72) P20.6@31.496,44.255 31.496,43.663 32.837,42.322 40.941,42.322 43.231,40.032 v1(43.231,37.617) ; v1(43.104,31.674) 44.145,30.632 44.145,28.955 47.193,25.907 47.193,19.66 47.754,19.099 U2.21@47.754,17.825
  Bottom Layer w0.152: v1(43.104,31.674) 43.104,37.49 v1(43.231,37.617)
  Bottom Layer w0.508: P26.6@31.496,44.255 v1(31.496,45.72) P26.6@31.496,47.185
SH_VTG: P20.3 P26.3 Q20.4 R22.1 | length 36.7
  Top Layer w0.152: P20.3@23.876,44.255 P20.3@23.876,47.185
  Top Layer w0.254: P20.3@23.876,44.255 v1(23.876,45.72) P20.3@23.876,47.185 ; R22.1@49.996,46.271 50.201,46.065 Q20.4@51.255,46.065
  Top Layer w0.508: v1(49.073,46.436) 49.83,46.436 R22.1@49.996,46.271
  Mid-Layer 2 w0.508: v1(23.876,45.72) 24.643,46.487 49.068,46.487 49.073,46.482 v1(49.073,46.436)
  Bottom Layer w0.508: P26.3@23.876,44.255 v1(23.876,45.72) P26.3@23.876,47.185
SHIELD_DETECT: R68.1 SB33.2 TP19.1 U7.10 | length 33.2
  Top Layer w0.152: SB33.2@65.702,27.94 64.524,27.94 R68.1@64.516,27.932 64.508,27.94 TP19.1@62.484,27.94 62.484,26.594 63.828,25.25 78.234,25.25 79.223,26.238 79.223,27.229 79.832,27.838 v1(80.264,27.838) ; v1(81.813,21.336) 82.14,21.009 U7.10@82.14,20.535
  Mid-Layer 2 w0.152: v1(80.264,27.838) 82.499,25.604 82.499,22.021 v1(81.813,21.336)
SWDCLK: P18.4 P25.4 SB55.1 U1.AA24 | length 86.2
  Top Layer w0.152: v1@61.374,19.736 61.392,19.754 v1(61.392,19.914) ; v1(63.349,24.078) 63.607,24.335 76.624,24.335 76.71,24.249 82.897,24.249 83.82,25.171 P18.4@83.82,25.99 83.82,26.773 84.429,27.381 v1(84.429,28.194) 84.429,32.36 83.82,32.968 P25.4@83.82,34.245 ; U1.AA24@118.414,35.367 118.496,35.367 122.174,31.689 122.174,30.886 v1@121.514,30.226
  Top Layer w0.203: v1(61.392,19.914) 62.001,19.914 62.238,19.677 62.238,19.327 SB55.1@62.238,18.974
  Bottom Layer w0.152: v1(61.392,19.914) 60.35,19.914 60.02,20.244 60.02,21.718 62.385,24.083 63.344,24.083 v1(63.349,24.078) ; v1(84.429,28.194) 85.064,27.559 86.056,27.559 87.402,28.905 95.25,28.905 95.707,29.362 96.844,29.362 98.322,27.884 110.415,27.884 111.258,28.728 118.338,28.728 119.837,30.226 v1(121.31,30.226)
SWDIO: P18.2 P25.2 SB54.1 U1.AC24 | length 88.3
  Top Layer w0.152: v1(61.443,17.45) 61.443,16.505 61.493,16.454 61.493,16.111 SB54.1@61.526,16.078 ; v1(62.81,24.616) 62.81,23.862 63.254,23.419 63.754,23.419 64.366,24.03 76.498,24.03 76.589,23.939 77.682,23.939 77.687,23.944 83.863,23.944 85.09,25.171 P18.2@85.09,25.99 85.09,26.773 85.699,27.381 85.699,32.843 85.09,33.452 P25.2@85.09,34.245 ; U1.AC24@118.414,34.867 118.565,34.867 121.869,31.563 121.869,31.012 121.616,30.759 v1(120.752,30.759)
  Bottom Layer w0.152: v1(61.443,17.45) 61.443,18.394 59.715,20.121 59.715,21.845 62.487,24.616 v1(62.81,24.616) ; v1@85.725,28.092 86.843,29.21 95.124,29.21 95.581,29.667 96.967,29.667 98.448,28.187 110.29,28.187 111.133,29.03 118.213,29.03 119.942,30.759 v1(120.752,30.759)
  other v1: 85.471,28.092
TCKOUT: R28.1 U2.14 U2.23 | length 8.9
  Top Layer w0.152: v1(44.254,19.197) 44.254,16.876 R28.1@44.772,16.358 ; v1(48.75,19.197) 48.75,17.837 48.758,17.829 U2.23@48.754,17.825
  Bottom Layer w0.152: v1(44.254,19.197) v1(48.75,19.197)
TMSOUT: R29.1 U2.17 | length 1.4
  Top Layer w0.152: R29.1@45.754,16.385 U2.17@45.754,17.825
TRACE_SW: R4.1 TP23.1 U8.2 U8.10 | length 37.8
  Top Layer w0.152: TP23.1@77.216,43.18 79.273,43.18 79.785,43.691 84.934,43.691 86.233,42.393 86.233,36.448 85.776,35.99 85.776,34.756 86.004,34.528 86.004,23.825 v2(85.903,23.724) ; U8.10@91.123,23.822 91.418,23.822 91.818,23.422 91.973,23.422 ; v2@91.973,23.114 91.973,23.422 ; U8.2@92.773,23.422 91.973,23.422
  Mid-Layer 1 w0.152: v2(85.903,23.724) 85.903,23.579 86.926,22.555 87.808,22.555 88.417,23.165 91.923,23.165 v2@91.999,23.089
  other v2: 91.999,23.063
USB_DETECT: Q40.3 R26.1 SB31.2 SW6.3 | length 130.1
  Top Layer w0.254: v2(10.566,60.071) 11.405,60.909 91.567,60.909 ; Q40.3@14.163,38.085 14.742,38.085 v2(15.113,38.456) ; R26.1@94.996,60.241 94.982,60.255 92.221,60.255 91.567,60.909 ; SW6.3@106.869,60.484 106.869,61.076 105.207,62.738 93.396,62.738 91.567,60.909
  Mid-Layer 1 w0.254: v1(8.28,53.721) 8.661,53.721 10.566,55.626 v2(10.566,60.071) ; v2(15.113,38.456) 15.646,38.989 v1(15.646,41.504)
  Bottom Layer w0.254: v1(8.28,53.721) 9.22,53.721 15.646,47.294 v1(15.646,41.504)
V5V: C81.2 C82.2 C83.2 C85.2 D84.1 P1.5 P5.2 P7.5 P11.2 P13.10 Q80.2 R80.2 R83.1 R93.1 TP36.1 U12.10 U19.8 | length 139.8
  Top Layer w0.254: 10.312,21.717 9.296,20.701 9.296,17.399 11.786,14.91 11.786,13.889 R83.1@11.782,13.886
  Top Layer w0.381: C85.2@27.856,28.194 28.727,28.194 v1(28.931,28.397) ; U19.8@27.893,26.756 C85.2@27.893,28.157
  Top Layer w0.508: C81.2@6.045,24.544 6.045,24.473 C83.2@8.663,24.473 ; C83.2@8.89,24.7 C82.2@10.084,24.7 10.66,24.7 U12.10@11.04,25.079 ; Q80.2@24.639,21.336 v1(24.639,22.046)
  Top Layer w0.635: C83.2@8.89,24.7 8.89,23.139 10.312,21.717 15.215,21.717 16.383,22.885 v1(18.923,22.885) 18.923,24.334 D84.1@19.507,24.918 ; R93.1@36.83,14.257 36.83,13.614 v1(37.49,12.954) ; P5.2@67.119,35.56 68.047,35.56 69.215,36.728 TP36.1@69.215,38.1
  Top Layer w0.762: P13.10@38.1,3.81 P1.5@38.1,6.155 v1(38.1,7.62) P1.5@38.1,9.085 ; P5.2@67.119,35.56 67.722,34.957 v1(67.722,34.296)
  Bottom Layer w0.508: 21.857,22.948 21.92,22.885 ; 24.639,22.81 24.714,22.885
  Bottom Layer w0.635: v1(37.49,12.954) 37.719,12.725 37.719,10.998
  Bottom Layer w0.762: v1(18.923,22.885) 21.92,22.885 24.714,22.885 26.645,22.885 28.499,24.74 28.499,27.965 v1(28.931,28.397) ; 24.639,22.81 v1(24.639,22.046) 25.857,20.828 25.857,20.015 27.47,18.402 27.47,13.83 30.302,10.998 36.187,10.998 ; P7.5@38.1,6.155 v1(38.1,7.62) P7.5@38.1,9.085 36.187,10.998 ; P11.2@67.722,35.56 v1(67.722,34.296) 69.514,34.296 70.028,33.782 70.028,23.868 69.901,23.741 69.901,23.707 59.097,12.903 40.437,12.903 38.532,10.998 37.719,10.998 36.187,10.998
VBAT: Bat1.1 SB35.2 TP26.1 U14.A1 U21.1 | length 64.6
  Top Layer w0.152: v1(15.697,13.716) 15.853,13.561 15.853,11.331 16.755,10.429 U21.1@17.922,10.429
  Top Layer w0.245: 20.498,14.043 U14.A1@20.831,14.043
  Top Layer w0.508: v1(16.205,16.154) 17.043,16.154 19.165,14.033 20.488,14.033
  Top Layer w0.61: v1(15.697,13.716) SB35.2@16.332,13.716
  Bottom Layer w0.508: Bat1.1@11.43,18.654 9.921,17.145 4.191,17.145 0.559,20.777 0.559,39.929 5.446,44.816 Bat1.1@11.43,44.816
  Bottom Layer w0.635: Bat1.1@11.43,18.654 13.65,16.434 14.757,16.434 15.037,16.154 ; v1(15.697,13.716) 15.037,14.376 15.037,16.154 ; v1(16.205,16.154) 15.037,16.154
  other v1: 0.711,38.1
VBAT_EN: U14.B2 U21.4 | length 8.1
  Top Layer w0.152: v2(18.44,11.709) 18.621,11.529 18.621,9.851 19.343,9.129 U21.4@19.822,9.129 ; U14.B2@21.231,13.643 21.488,13.386 v2(21.488,13.106)
  Mid-Layer 1 w0.152: v2(18.44,11.709) 20.345,13.614 21.005,13.614 21.488,13.131 v2(21.488,13.106)
VBOOST_SRC: C80.2 L80.2 SW8.6 TP28.1 U12.1 U12.6 | length 37.2
  Top Layer w0.152: v2(10.516,27.432) 11.056,27.432 U12.6@11.074,27.414 ; U12.1@13.614,25.114 v2(14.09,25.114)
  Top Layer w0.508: 13.614,24.816 13.614,23.871 C80.2@13.315,23.571 ; TP28.1@14.757,22.682 14.63,22.555 v1(13.868,22.555) 13.538,22.555 13.273,22.82 C80.2@13.273,23.571 C80.2@13.315,23.571 ; L80.2@16.104,24.833 15.435,24.833 14.173,23.571 C80.2@13.315,23.571
  Top Layer w1.016: SW8.6@3.028,8.109 3.028,7.529 4.258,6.299 v1(6.518,6.299)
  Mid-Layer 1 w0.152: v2(10.516,27.432) 12.834,25.114 v2(14.09,25.114)
  Mid-Layer 2 w1.016: v1(6.518,6.299) 7.518,6.299 11.786,10.566 11.786,16.84 13.868,18.923 v1(13.868,22.555)
VBOOST_SRC': D80.1 D81.1 D82.1 D83.1 SW8.5 TP32.1 | length 34.7
  Top Layer w1.016: SW8.5@5.528,8.109 v1(6.576,8.109) ; v1@21.311,29.718 22.022,29.007 25.349,29.007
  Mid-Layer 2 w1.016: v1(6.576,8.109) 7.347,8.109 9.779,10.541 9.779,16.713 11.862,18.796 11.862,22.225 19.291,29.654 v1@21.336,29.654
  other v1: 21.209,29.845
VBUS: C69.2 D80.2 FB61.2 J4.5 Q40.2 R40.1 | length 78.4
  Top Layer w0.254: 11.665,40.329 13.259,38.735 ; R40.1@14.13,36.932 13.665,36.932 13.259,37.338 13.259,38.735 ; Q40.2@14.163,38.735 13.259,38.735
  Top Layer w0.635: v1(23.774,30.836) 23.8,30.81 D80.2@23.8,30.186
  Top Layer w0.762: J4.5@60.325,45.72 v1(61.087,45.72)
  Top Layer w1.016: 4.923,38.011 4.923,39.441 5.811,40.329 6.444,40.329 6.452,40.322 7.251,40.322 7.259,40.329 11.665,40.329 18.206,40.329 v1(18.237,40.361)
  Mid-Layer 2 w0.508: 23.978,38.252 24.206,38.481 24.206,40.894 v1(25.933,42.621) ; v1(30.328,42.621) 50.597,42.621 51.968,43.993 v1(55.651,43.993)
  Mid-Layer 2 w1.016: v1(18.237,40.361) 18.771,39.827 22.403,39.827 23.978,38.252 23.978,37.084 23.114,36.22 23.114,32.614 23.774,31.953 v1(23.774,30.836)
  Bottom Layer w0.508: v1(25.933,42.621) v1(30.328,42.621) ; v1(55.651,43.993) 55.88,43.993 57.545,45.658 61.025,45.658 v1(61.087,45.72)
VBUS_NRF: C21.1 SB80.1 TP38.1 U1.AD2 U22.1 | length 47.6
  Top Layer w0.25: U1.AD2@112.414,34.367 112.414,32.742 C21.1@112.539,32.617 v1@113.053,32.103
  Top Layer w0.508: 86.656,12.878 86.272,12.878 U22.1@85.253,13.898 85.253,14.133 TP38.1@86.36,15.24 86.614,14.986 v1(88.646,14.986)
  Mid-Layer 2 w0.508: v1(106.172,13.894) 111.531,19.253 111.531,27.732 113.055,29.256 v1(113.055,32.106)
  Bottom Layer w0.508: v1(88.646,14.986) 90.678,14.986 91.77,13.894 v1(106.172,13.894)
